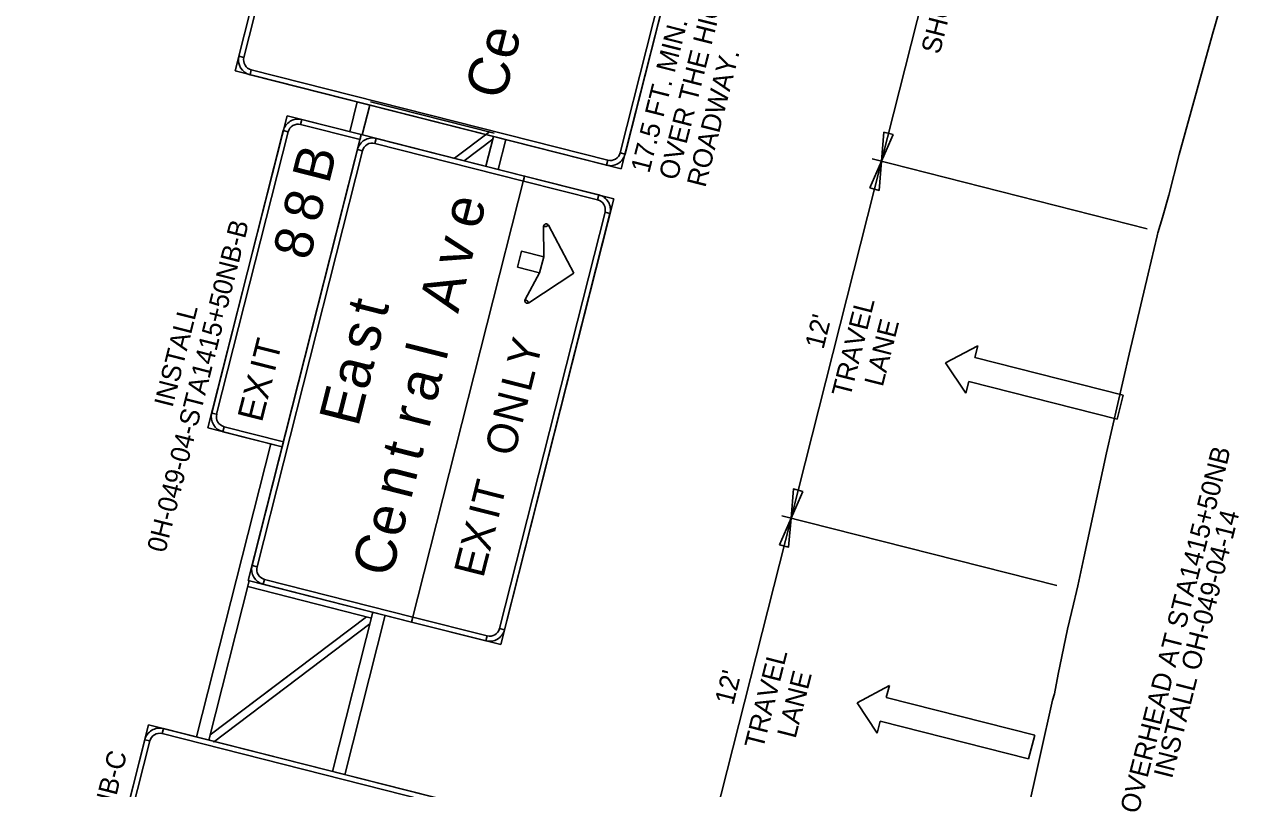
# Model space of a CAD drawing. Extents: x 670010 to 670131, y 737834 to 738002.
# Drawn here: x 670064.27 to 670103.9, y 737882.11 to 737907.03 of the extents above; entities that cross this region are included whole.
import ezdxf

# ---------------------------------------------------------------- set-up
doc = ezdxf.new("R2010")
doc.units = 0
for name, color, linetype in [('R_Exist Surface', 7, 'Continuous'), ('R_Horz Alg Annot', 7, 'Continuous'), ('R_MOT', 7, 'Continuous'), ('R_SIGN', 7, 'Continuous'), ('R_SIGN_ANNOT', 7, 'Continuous')]:
    doc.layers.add(name, color=color, linetype=linetype)

msp = doc.modelspace()

# ---------------------------------------------------------------- linework, layer by layer
at = {"layer": 'R_Exist Surface'}
msp.add_lwpolyline([(670096.512, 737879.088), (670097.416, 737883.191), (670097.828, 737884.997), (670097.884, 737885.204), (670098.01, 737885.844), (670098.313, 737887.311), (670098.503, 737888.128), (670098.604, 737888.542), (670098.649, 737888.723), (670098.842, 737889.638), (670099.588, 737893.062), (670100.33, 737896.273), (670100.944, 737898.895), (670101.242, 737900.132), (670101.255, 737900.185), (670101.266, 737900.23), (670101.415, 737900.733), (670101.616, 737901.467), (670101.956, 737902.785), (670102.539, 737904.902), (670103.044, 737906.711), (670103.578, 737908.556)], dxfattribs=at)
at = {"layer": 'R_Horz Alg Annot'}
for p, q in [((670092.241, 737902.566), (670095.191, 737914.198)), ((670089.291, 737890.934), (670092.241, 737902.566)), ((670100.914, 737900.366), (670091.938, 737902.643)), ((670086.355, 737879.359), (670089.291, 737890.934)), ((670097.964, 737888.734), (670088.988, 737891.011))]:
    msp.add_line(p, q, dxfattribs=at)
for points in [[(670092.623, 737903.436), (670092.241, 737902.566), (670092.32, 737903.513)], [(670091.859, 737901.696), (670092.241, 737902.566), (670092.162, 737901.619)], [(670089.673, 737891.804), (670089.291, 737890.934), (670089.37, 737891.881)], [(670088.909, 737890.064), (670089.291, 737890.934), (670089.212, 737889.987)]]:
    msp.add_lwpolyline(points, close=True, dxfattribs=at)
at = {"layer": 'R_MOT'}
for p, q in [((670095.382, 737896.553), (670094.335, 737895.993)), ((670095.284, 737896.165), (670095.382, 737896.553)), ((670094.335, 737895.993), (670094.989, 737895.002)), ((670100.127, 737894.937), (670095.284, 737896.165)), ((670094.989, 737895.002), (670095.087, 737895.39)), ((670095.087, 737895.39), (670099.93, 737894.162)), ((670099.93, 737894.162), (670100.127, 737894.937)), ((670092.498, 737885.469), (670091.451, 737884.91)), ((670092.399, 737885.082), (670092.498, 737885.469)), ((670091.451, 737884.91), (670092.104, 737883.918)), ((670097.242, 737883.853), (670092.399, 737885.082)), ((670092.104, 737883.918), (670092.203, 737884.306)), ((670092.203, 737884.306), (670097.045, 737883.078)), ((670097.045, 737883.078), (670097.242, 737883.853))]:
    msp.add_line(p, q, dxfattribs=at)
at = {"layer": 'R_SIGN'}
for p, q in [((670074.836, 737920.051), (670071.148, 737905.512)), ((670083.749, 737902.316), (670087.437, 737916.855)), ((670071.433, 737905.955), (670071.271, 737905.996)), ((670071.148, 737905.512), (670083.749, 737902.316)), ((670071.633, 737905.389), (670071.674, 737905.55)), ((670074.888, 737903.531), (670075.134, 737904.501)), ((670075.292, 737903.429), (670075.538, 737904.398)), ((670079.605, 737903.485), (670075.566, 737904.51)), ((670072.841, 737904.051), (670070.26, 737893.873)), ((670075.264, 737903.436), (670072.841, 737904.051)), ((670073.285, 737903.766), (670073.326, 737903.928)), ((670072.718, 737903.566), (670072.88, 737903.525)), ((670078.307, 737902.664), (670079.449, 737903.525)), ((670075.264, 737903.436), (670071.577, 737888.896)), ((670072.683, 737893.258), (670075.264, 737903.436)), ((670080.596, 737902.084), (670075.264, 737903.436)), ((670075.708, 737903.151), (670075.749, 737903.313)), ((670078.618, 737902.585), (670079.556, 737903.292)), ((670079.331, 737902.405), (670079.577, 737903.374)), ((670079.735, 737902.302), (670079.98, 737903.272)), ((670075.142, 737902.951), (670075.303, 737902.91)), ((670083.872, 737902.8), (670083.711, 737902.841)), ((670083.306, 737902.6), (670083.265, 737902.439)), ((670076.908, 737887.544), (670080.596, 737902.084)), ((670080.596, 737902.084), (670076.908, 737887.544)), ((670083.504, 737901.346), (670080.596, 737902.084)), ((670083.749, 737902.316), (670083.749, 737902.316)), ((670079.816, 737886.807), (670083.504, 737901.346)), ((670083.019, 737901.469), (670082.978, 737901.308)), ((670083.219, 737900.903), (670083.381, 737900.862)), ((670081.213, 737900.441), (670081.297, 737900.441)), ((670081.297, 737900.441), (670081.37, 737900.481)), ((670080.682, 737898.018), (670080.609, 737898.058)), ((670080.727, 737897.948), (670080.682, 737898.018)), ((670070.544, 737894.316), (670070.383, 737894.357)), ((670070.26, 737893.873), (670072.683, 737893.258)), ((670070.745, 737893.75), (670070.786, 737893.911)), ((670072.307, 737893.354), (670069.882, 737883.795)), ((670072.683, 737893.258), (670072.683, 737893.258)), ((670071.861, 737889.34), (670071.7, 737889.381)), ((670071.604, 737888.889), (670070.286, 737883.692)), ((670071.577, 737888.896), (670076.908, 737887.544)), ((670072.062, 737888.773), (670072.103, 737888.935)), ((670075.595, 737887.673), (670071.556, 737888.698)), ((670070.33, 737883.863), (670075.439, 737887.713)), ((670075.643, 737887.865), (670074.325, 737882.668)), ((670076.047, 737887.763), (670074.729, 737882.565)), ((670070.436, 737883.63), (670075.545, 737887.48)), ((670076.908, 737887.544), (670076.908, 737887.544)), ((670076.908, 737887.544), (670079.816, 737886.807)), ((670079.939, 737887.291), (670079.777, 737887.332)), ((670079.372, 737887.091), (670079.331, 737886.93)), ((670079.816, 737886.807), (670079.816, 737886.807)), ((670070.33, 737883.863), (670072.908, 737885.805)), ((670070.436, 737883.63), (670073.218, 737885.726)), ((670068.32, 737884.191), (670065.247, 737872.075)), ((670078.498, 737881.61), (670068.32, 737884.191)), ((670068.197, 737883.706), (670068.359, 737883.665)), ((670068.764, 737883.906), (670068.805, 737884.068))]:
    msp.add_line(p, q, dxfattribs=at)
for points in [[(670074.875, 737919.526), (670071.433, 737905.955), (670071.271, 737905.996), (670074.713, 737919.567), (670074.875, 737919.526)], [(670083.711, 737902.841), (670087.153, 737916.412), (670087.314, 737916.371), (670083.872, 737902.8), (670083.711, 737902.841)], [(670071.674, 737905.55), (670083.306, 737902.6), (670083.265, 737902.439), (670071.633, 737905.389), (670071.674, 737905.55)], [(670075.224, 737903.274), (670073.285, 737903.766), (670073.326, 737903.928), (670075.264, 737903.436), (670075.224, 737903.274)], [(670072.88, 737903.525), (670070.544, 737894.316), (670070.383, 737894.357), (670072.718, 737903.566), (670072.88, 737903.525)], [(670080.555, 737901.922), (670075.708, 737903.151), (670075.749, 737903.313), (670080.596, 737902.084), (670080.555, 737901.922)], [(670075.303, 737902.91), (670071.861, 737889.34), (670071.7, 737889.381), (670075.142, 737902.951), (670075.303, 737902.91)], [(670082.978, 737901.308), (670080.555, 737901.922), (670080.596, 737902.084), (670083.019, 737901.469), (670082.978, 737901.308)], [(670079.777, 737887.332), (670083.219, 737900.903), (670083.381, 737900.862), (670079.939, 737887.291), (670079.777, 737887.332)], [(670082.201, 737898.922), (670081.37, 737900.481), (670081.297, 737900.441), (670081.213, 737900.441), (670081.218, 737899.451), (670081.084, 737898.926), (670080.609, 737898.058), (670080.682, 737898.018), (670080.727, 737897.948), (670082.201, 737898.922)], [(670080.357, 737899.11), (670080.491, 737899.635), (670081.218, 737899.451), (670081.084, 737898.926), (670080.357, 737899.11)], [(670070.786, 737893.911), (670072.724, 737893.42), (670072.683, 737893.258), (670070.745, 737893.75), (670070.786, 737893.911)], [(670072.103, 737888.935), (670076.949, 737887.706), (670076.908, 737887.544), (670072.062, 737888.773), (670072.103, 737888.935)], [(670076.949, 737887.706), (670079.372, 737887.091), (670079.331, 737886.93), (670076.908, 737887.544), (670076.949, 737887.706)], [(670068.359, 737883.665), (670065.532, 737872.518), (670065.37, 737872.559), (670068.197, 737883.706), (670068.359, 737883.665)], [(670077.972, 737881.571), (670068.764, 737883.906), (670068.805, 737884.068), (670078.013, 737881.732), (670077.972, 737881.571)]]:
    msp.add_lwpolyline(points, close=True, dxfattribs=at)
for centre, radius, start, end in [((670071.756, 737905.873), 0.5, 165.7688, 255.7684), ((670071.756, 737905.873), 0.333, 165.7688, 255.7684), ((670073.203, 737903.443), 0.5, 75.7686, 165.7688), ((670073.203, 737903.443), 0.333, 75.7686, 165.7688), ((670075.626, 737902.828), 0.5, 75.7686, 165.7688), ((670075.626, 737902.828), 0.333, 75.7686, 165.7688), ((670083.388, 737902.923), 0.5, 255.7684, 345.7686), ((670083.388, 737902.923), 0.333, 255.7684, 345.7686), ((670082.896, 737900.985), 0.333, 345.7686, 75.7688), ((670082.896, 737900.985), 0.5, 345.7686, 75.7688), ((670081.297, 737900.441), 0.0833, 28.7937, 180.2414), ((670080.682, 737898.018), 0.0833, 151.2958, 302.7435), ((670070.867, 737894.235), 0.5, 165.7688, 255.7684), ((670070.867, 737894.235), 0.333, 165.7688, 255.7684), ((670072.184, 737889.258), 0.5, 165.7688, 255.7684), ((670072.184, 737889.258), 0.333, 165.7688, 255.7684), ((670079.454, 737887.414), 0.5, 255.7684, 345.7686), ((670079.454, 737887.414), 0.333, 255.7684, 345.7686), ((670068.682, 737883.583), 0.5, 75.7686, 165.7688), ((670068.682, 737883.583), 0.333, 75.7686, 165.7688)]:
    msp.add_arc(centre, radius, start, end, dxfattribs=at)

# ---------------------------------------------------------------- texts
at = {"layer": 'R_Horz Alg Annot'}
for p in [(670090.344, 737896.41), (670087.401, 737884.807)]:
    msp.add_text("12'", height=0.63, rotation=75.7686, dxfattribs=at).set_placement(p)
at = {"layer": 'R_SIGN'}
for s, height, p in [('e', 1.333, (670080.252, 737905.823)), ('C', 1.333, (670079.924, 737904.531)), ('B', 1.25, (670074.205, 737901.8)), ('8', 1.25, (670073.882, 737900.528)), ('e', 1.333, (670079.113, 737900.307)), ('8', 1.25, (670073.572, 737899.304)), ('v', 1.333, (670078.795, 737899.053)), ('A', 1.333, (670078.422, 737897.58)), ('t', 1.333, (670076.055, 737897.402)), ('s', 1.333, (670075.774, 737896.291)), ('T', 0.833, (670072.517, 737895.991)), ('Y', 1, (670080.975, 737895.784)), ('l', 1.333, (670078.028, 737896.029)), ('I', 0.833, (670072.433, 737895.66)), ('a', 1.333, (670075.462, 737895.063)), ('X', 0.833, (670072.204, 737894.759)), ('a', 1.333, (670077.681, 737894.659)), ('L', 1, (670080.779, 737895.008)), ('E', 1.333, (670075.161, 737893.874)), ('E', 0.833, (670072.019, 737894.028)), ('N', 1, (670080.511, 737893.952)), ('r', 1.333, (670077.468, 737893.819)), ('O', 1, (670080.245, 737892.905)), ('t', 1.333, (670077.193, 737892.734)), ('n', 1.333, (670076.881, 737891.506)), ('T', 1, (670079.817, 737891.218)), ('e', 1.333, (670076.563, 737890.252)), ('I', 1, (670079.724, 737890.85)), ('X', 1, (670079.458, 737889.803)), ('C', 1.333, (670076.235, 737888.96)), ('E', 1, (670079.242, 737888.95))]:
    msp.add_text(s, height=height, rotation=75.7686, dxfattribs=at).set_placement(p)
at = {"layer": 'R_SIGN_ANNOT'}
for s, height, p in [('17.5 FT. MIN. VERTICAL CLEARANCE ', 0.63, (670084.658, 737902.152)), ('OVER THE HIGHEST POINT OF THE ', 0.63, (670085.574, 737901.92)), ('SHOULDER', 0.63, (670094.137, 737906.028)), ('ROADWAY.', 0.63, (670086.49, 737901.687)), ('0H-049-04-STA1415+50NB-B', 0.625, (670068.866, 737889.776)), ('TRAVEL', 0.63, (670091.219, 737894.845)), ('INSTALL ', 0.625, (670069.1, 737894.512)), ('LANE', 0.63, (670092.281, 737895.189)), ('OVERHEAD AT STA1415+50NB', 0.625, (670100.624, 737881.265)), ('INSTALL OH-049-04-14', 0.625, (670101.722, 737882.41)), ('TRAVEL', 0.63, (670088.372, 737883.375)), ('LANE', 0.63, (670089.434, 737883.72)), ('OH-049-04-STA1415+50NB-C', 0.625, (670064.833, 737872.248))]:
    msp.add_text(s, height=height, rotation=75.7686, dxfattribs=at).set_placement(p)

doc.saveas('drawing.dxf')
